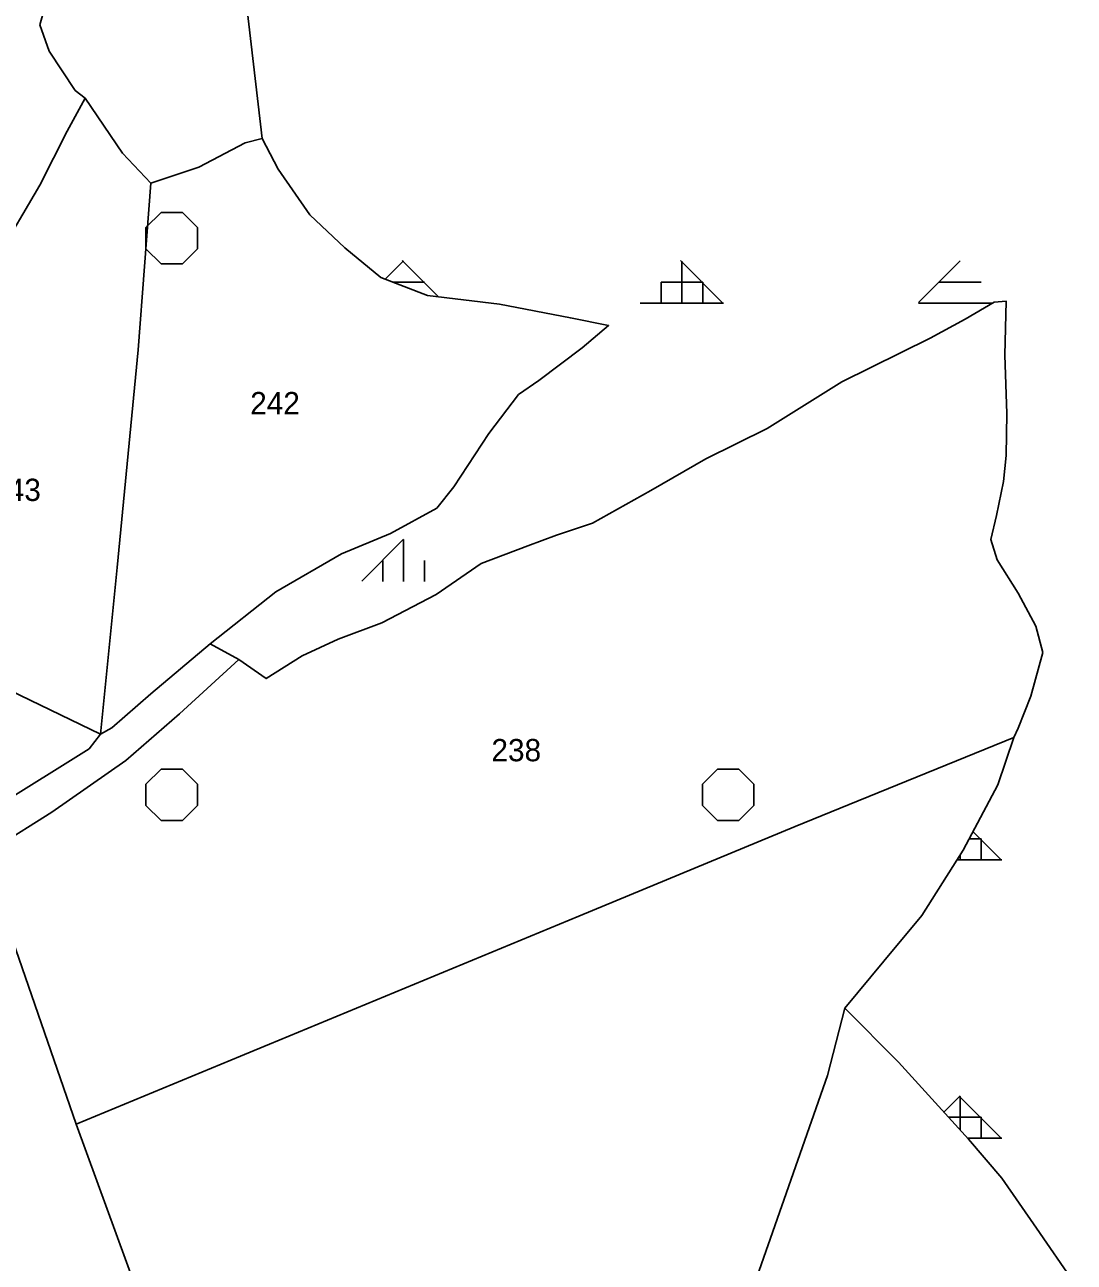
# Model space of a CAD drawing. Extents: x 410727 to 412947, y 4463506 to 4466382.
# Drawn here: x 412194.6 to 412383.2, y 4465413.6 to 4465635.8 of the extents above; entities that cross this region are included whole.
import ezdxf

# ---------------------------------------------------------------- set-up
doc = ezdxf.new("R2010")
doc.units = 0
for name, color, linetype in [('ADAKENARI', 7, 'Continuous'), ('KDS_PARSEL_NO', 7, 'Continuous'), ('KDS_PL', 7, 'Continuous'), ('PL_AYA_ORMAN', 7, 'Continuous'), ('PL_KA_TARIM_DIGER', 7, 'Continuous'), ('TR_ORMAN', 7, 'Continuous'), ('TR_TARIMALANI', 7, 'Continuous')]:
    doc.layers.add(name, color=color, linetype=linetype)

msp = doc.modelspace()

# ---------------------------------------------------------------- linework, layer by layer
at = {"layer": 'ADAKENARI'}
for p, q in [((412237.26, 4465615.42), (412234.44, 4465639.54)), ((412240.11, 4465609.88), (412237.26, 4465615.42)), ((412245.82, 4465601.68), (412240.11, 4465609.88)), ((412252.1, 4465595.77), (412245.82, 4465601.68)), ((412258.58, 4465590.43), (412252.1, 4465595.77)), ((412266.95, 4465587.19), (412258.58, 4465590.43)), ((412279.89, 4465585.66), (412266.95, 4465587.19)), ((412292.65, 4465583.18), (412279.89, 4465585.66)), ((412368.8, 4465586.04), (412363.6, 4465582.99)), ((412370.95, 4465586.17), (412368.8, 4465586.04)), ((412370.7, 4465576.52), (412370.95, 4465586.17)), ((412299.5, 4465581.85), (412292.65, 4465583.18)), ((412363.6, 4465582.99), (412357.27, 4465579.57)), ((412294.74, 4465577.84), (412299.5, 4465581.85)), ((412286.94, 4465571.93), (412294.74, 4465577.84)), ((412357.27, 4465579.57), (412341.44, 4465571.7)), ((412371.08, 4465565.99), (412370.7, 4465576.52)), ((412283.32, 4465569.45), (412286.94, 4465571.93)), ((412341.44, 4465571.7), (412328.02, 4465563.33)), ((412277.99, 4465562.4), (412283.32, 4465569.45)), ((412370.95, 4465558.5), (412371.08, 4465565.99)), ((412271.71, 4465552.86), (412277.99, 4465562.4)), ((412328.02, 4465563.33), (412317, 4465557.87)), ((412317, 4465557.87), (412307.12, 4465552.16)), ((412370.45, 4465553.81), (412370.95, 4465558.5)), ((412369.18, 4465547.72), (412370.45, 4465553.81)), ((412268.66, 4465549.04), (412271.71, 4465552.86)), ((412307.12, 4465552.16), (412296.61, 4465546.32)), ((412260.29, 4465544.47), (412268.66, 4465549.04)), ((412368.17, 4465543.4), (412369.18, 4465547.72)), ((412251.53, 4465540.84), (412260.29, 4465544.47)), ((412296.61, 4465546.32), (412290.15, 4465544.16)), ((412284.96, 4465542.26), (412276.6, 4465539.09)), ((412290.15, 4465544.16), (412284.96, 4465542.26)), ((412290.15, 4465544.16), (412284.96, 4465542.26)), ((412369.3, 4465539.72), (412368.17, 4465543.4)), ((412239.73, 4465533.98), (412251.53, 4465540.84)), ((412276.6, 4465539.09), (412268.5, 4465533.51)), ((412373.1, 4465533.76), (412369.3, 4465539.72)), ((412227.93, 4465524.63), (412239.73, 4465533.98)), ((412268.5, 4465533.51), (412258.74, 4465528.43)), ((412376.27, 4465527.79), (412373.1, 4465533.76)), ((412258.74, 4465528.43), (412250.89, 4465525.51)), ((412377.54, 4465523.1), (412376.27, 4465527.79)), ((412233.04, 4465521.83), (412227.93, 4465524.63)), ((412250.89, 4465525.51), (412244.43, 4465522.47)), ((412244.43, 4465522.47), (412237.98, 4465518.41)), ((412375.38, 4465515.23), (412377.54, 4465523.1)), ((412237.98, 4465518.41), (412233.04, 4465521.83)), ((412373.1, 4465509.52), (412375.38, 4465515.23)), ((412372.33, 4465507.8), (412373.1, 4465509.52)), ((412372.33, 4465507.8), (412373.1, 4465509.52)), ((412369.44, 4465499.29), (412372.33, 4465507.8)), ((412363.22, 4465487.58), (412369.44, 4465499.29)), ((412355.78, 4465475.87), (412363.22, 4465487.58)), ((412348.96, 4465467.64), (412355.78, 4465475.87)), ((412341.94, 4465459.2), (412348.96, 4465467.64)), ((412351.61, 4465449.5), (412341.94, 4465459.2)), ((412364.2, 4465435.68), (412351.61, 4465449.5)), ((412370.19, 4465428.68), (412364.2, 4465435.68)), ((412376.38, 4465419.67), (412370.19, 4465428.68)), ((412383.18, 4465409.86), (412376.38, 4465419.67))]:
    msp.add_line(p, q, dxfattribs=at)
at = {"layer": 'KDS_PL'}
for p, q in [((412198.76, 4465640.96), (412197.27, 4465635.83)), ((412197.27, 4465635.83), (412198.98, 4465631.12)), ((412198.98, 4465631.12), (412203.67, 4465624.06)), ((412202.23, 4465616.75), (412205.47, 4465622.66)), ((412203.67, 4465624.06), (412205.47, 4465622.66)), ((412205.47, 4465622.66), (412212.13, 4465612.75)), ((412197.29, 4465607.03), (412202.23, 4465616.75)), ((412234.21, 4465614.65), (412237.26, 4465615.42)), ((412237.26, 4465615.42), (412240.11, 4465609.88)), ((412225.84, 4465610.27), (412234.21, 4465614.65)), ((412212.13, 4465612.75), (412217.27, 4465607.41)), ((412217.27, 4465607.41), (412225.84, 4465610.27)), ((412240.11, 4465609.88), (412245.82, 4465601.68)), ((412182.06, 4465581.09), (412197.29, 4465607.03)), ((412217.27, 4465607.41), (412214.99, 4465577.46)), ((412245.82, 4465601.68), (412252.1, 4465595.77)), ((412252.1, 4465595.77), (412258.58, 4465590.43)), ((412258.58, 4465590.43), (412266.95, 4465587.19)), ((412266.95, 4465587.19), (412279.89, 4465585.66)), ((412279.89, 4465585.66), (412292.65, 4465583.18)), ((412363.6, 4465582.99), (412368.8, 4465586.04)), ((412368.8, 4465586.04), (412370.95, 4465586.17)), ((412370.95, 4465586.17), (412370.7, 4465576.52)), ((412292.65, 4465583.18), (412299.5, 4465581.85)), ((412357.27, 4465579.57), (412363.6, 4465582.99)), ((412299.5, 4465581.85), (412294.74, 4465577.84)), ((412294.74, 4465577.84), (412286.94, 4465571.93)), ((412341.44, 4465571.7), (412357.27, 4465579.57)), ((412214.99, 4465577.46), (412211.18, 4465538.37)), ((412370.7, 4465576.52), (412371.08, 4465565.99)), ((412286.94, 4465571.93), (412283.32, 4465569.45)), ((412328.02, 4465563.33), (412341.44, 4465571.7)), ((412283.32, 4465569.45), (412277.99, 4465562.4)), ((412371.08, 4465565.99), (412370.95, 4465558.5)), ((412277.99, 4465562.4), (412271.71, 4465552.86)), ((412317, 4465557.87), (412328.02, 4465563.33)), ((412307.12, 4465552.16), (412317, 4465557.87)), ((412370.95, 4465558.5), (412370.45, 4465553.81)), ((412370.45, 4465553.81), (412369.18, 4465547.72)), ((412271.71, 4465552.86), (412268.66, 4465549.04)), ((412296.61, 4465546.32), (412307.12, 4465552.16)), ((412268.66, 4465549.04), (412260.29, 4465544.47)), ((412369.18, 4465547.72), (412368.17, 4465543.4)), ((412260.29, 4465544.47), (412251.53, 4465540.84)), ((412290.15, 4465544.16), (412296.61, 4465546.32)), ((412276.6, 4465539.09), (412284.96, 4465542.26)), ((412284.96, 4465542.26), (412290.15, 4465544.16)), ((412368.17, 4465543.4), (412369.3, 4465539.72)), ((412251.53, 4465540.84), (412239.73, 4465533.98)), ((412211.18, 4465538.37), (412208.18, 4465508.42)), ((412268.5, 4465533.51), (412276.6, 4465539.09)), ((412369.3, 4465539.72), (412373.1, 4465533.76)), ((412239.73, 4465533.98), (412227.93, 4465524.63)), ((412258.74, 4465528.43), (412268.5, 4465533.51)), ((412373.1, 4465533.76), (412376.27, 4465527.79)), ((412250.89, 4465525.51), (412258.74, 4465528.43)), ((412376.27, 4465527.79), (412377.54, 4465523.1)), ((412227.93, 4465524.63), (412217.27, 4465515.67)), ((412227.93, 4465524.63), (412233.04, 4465521.83)), ((412244.43, 4465522.47), (412250.89, 4465525.51)), ((412237.98, 4465518.41), (412244.43, 4465522.47)), ((412377.54, 4465523.1), (412375.38, 4465515.23)), ((412222.4, 4465512.06), (412233.04, 4465521.83)), ((412233.04, 4465521.83), (412237.98, 4465518.41)), ((412208.18, 4465508.42), (412191.95, 4465516.24)), ((412217.27, 4465515.67), (412210.23, 4465509.57)), ((412375.38, 4465515.23), (412373.1, 4465509.52)), ((412212.77, 4465503.68), (412222.4, 4465512.06)), ((412210.23, 4465509.57), (412208.18, 4465508.42)), ((412373.1, 4465509.52), (412372.33, 4465507.8)), ((412206.17, 4465505.77), (412208.18, 4465508.42)), ((412372.33, 4465507.8), (412342.73, 4465495.79)), ((412369.44, 4465499.29), (412372.33, 4465507.8)), ((412173.15, 4465485.18), (412206.17, 4465505.77)), ((412199.48, 4465494.42), (412212.77, 4465503.68)), ((412363.22, 4465487.58), (412369.44, 4465499.29)), ((412342.73, 4465495.79), (412333.02, 4465491.83)), ((412186.94, 4465486.55), (412199.48, 4465494.42)), ((412333.02, 4465491.83), (412294.16, 4465475.71)), ((412355.78, 4465475.87), (412363.22, 4465487.58)), ((412203.85, 4465438.37), (412187.36, 4465485.9)), ((412294.16, 4465475.71), (412203.85, 4465438.37)), ((412348.96, 4465467.64), (412355.78, 4465475.87)), ((412341.94, 4465459.2), (412348.96, 4465467.64)), ((412338.85, 4465447.1), (412341.94, 4465459.2)), ((412341.94, 4465459.2), (412351.61, 4465449.5)), ((412351.61, 4465449.5), (412364.2, 4465435.68)), ((412324.53, 4465406.29), (412338.85, 4465447.1)), ((412203.85, 4465438.37), (412217.2, 4465401.77)), ((412364.2, 4465435.68), (412370.19, 4465428.68)), ((412370.19, 4465428.68), (412376.38, 4465419.67)), ((412376.38, 4465419.67), (412383.18, 4465409.86))]:
    msp.add_line(p, q, dxfattribs=at)
at = {"layer": 'PL_AYA_ORMAN'}
msp.add_lwpolyline([(412234.44, 4465639.54), (412237.26, 4465615.42), (412240.11, 4465609.88), (412245.82, 4465601.68), (412252.1, 4465595.77), (412258.58, 4465590.43), (412266.95, 4465587.19), (412279.89, 4465585.66), (412292.65, 4465583.18), (412299.5, 4465581.85), (412294.74, 4465577.84), (412286.94, 4465571.93), (412283.32, 4465569.45), (412277.99, 4465562.4), (412271.71, 4465552.86), (412268.66, 4465549.04), (412260.29, 4465544.47), (412251.53, 4465540.84), (412239.73, 4465533.98), (412227.93, 4465524.63), (412233.04, 4465521.83), (412237.98, 4465518.41), (412244.43, 4465522.47), (412250.89, 4465525.51), (412258.74, 4465528.43), (412268.5, 4465533.51), (412276.6, 4465539.09), (412284.96, 4465542.26), (412290.15, 4465544.16), (412296.61, 4465546.32), (412307.12, 4465552.16), (412317, 4465557.87), (412328.02, 4465563.33), (412341.44, 4465571.7), (412357.27, 4465579.57), (412363.6, 4465582.99), (412368.8, 4465586.04), (412370.95, 4465586.17), (412370.7, 4465576.52), (412371.08, 4465565.99), (412370.95, 4465558.5), (412370.45, 4465553.81), (412369.18, 4465547.72), (412368.17, 4465543.4), (412369.3, 4465539.72), (412373.1, 4465533.76), (412376.27, 4465527.79), (412377.54, 4465523.1), (412375.38, 4465515.23), (412373.1, 4465509.52), (412372.33, 4465507.8), (412369.44, 4465499.29), (412363.22, 4465487.58), (412355.78, 4465475.87), (412348.96, 4465467.64), (412341.94, 4465459.2), (412351.61, 4465449.5), (412364.2, 4465435.68), (412370.19, 4465428.68), (412376.38, 4465419.67), (412383.18, 4465409.86)], dxfattribs=at)
at = {"layer": 'PL_KA_TARIM_DIGER'}
msp.add_lwpolyline([(412234.44, 4465639.54), (412237.26, 4465615.42), (412240.11, 4465609.88), (412245.82, 4465601.68), (412252.1, 4465595.77), (412258.58, 4465590.43), (412266.95, 4465587.19), (412279.89, 4465585.66), (412292.65, 4465583.18), (412299.5, 4465581.85), (412294.74, 4465577.84), (412286.94, 4465571.93), (412283.32, 4465569.45), (412277.99, 4465562.4), (412271.71, 4465552.86), (412268.66, 4465549.04), (412260.29, 4465544.47), (412251.53, 4465540.84), (412239.73, 4465533.98), (412227.93, 4465524.63), (412233.04, 4465521.83), (412237.98, 4465518.41), (412244.43, 4465522.47), (412250.89, 4465525.51), (412258.74, 4465528.43), (412268.5, 4465533.51), (412276.6, 4465539.09), (412284.96, 4465542.26), (412290.15, 4465544.16), (412296.61, 4465546.32), (412307.12, 4465552.16), (412317, 4465557.87), (412328.02, 4465563.33), (412341.44, 4465571.7), (412357.27, 4465579.57), (412363.6, 4465582.99), (412368.8, 4465586.04), (412370.95, 4465586.17), (412370.7, 4465576.52), (412371.08, 4465565.99), (412370.95, 4465558.5), (412370.45, 4465553.81), (412369.18, 4465547.72), (412368.17, 4465543.4), (412369.3, 4465539.72), (412373.1, 4465533.76), (412376.27, 4465527.79), (412377.54, 4465523.1), (412375.38, 4465515.23), (412373.1, 4465509.52), (412372.33, 4465507.8), (412369.44, 4465499.29), (412363.22, 4465487.58), (412355.78, 4465475.87), (412348.96, 4465467.64), (412341.94, 4465459.2), (412351.61, 4465449.5), (412364.2, 4465435.68), (412370.19, 4465428.68), (412376.38, 4465419.67), (412383.18, 4465409.86)], dxfattribs=at)
at = {"layer": 'TR_ORMAN'}
for p, q in [((412259.37, 4465590.12), (412262.66, 4465593.41)), ((412259.37, 4465590.12), (412262.66, 4465593.41)), ((412268.94, 4465586.96), (412262.41, 4465593.48)), ((412268.94, 4465586.96), (412262.41, 4465593.48)), ((412319.9, 4465585.98), (412312.4, 4465593.48)), ((412319.9, 4465585.98), (412312.4, 4465593.48)), ((412312.67, 4465585.86), (412312.67, 4465593.36)), ((412312.67, 4465585.86), (412312.67, 4465593.36)), ((412355.16, 4465585.93), (412362.66, 4465593.43)), ((412260.7, 4465589.61), (412266.42, 4465589.61)), ((412260.7, 4465589.61), (412266.42, 4465589.61)), ((412308.92, 4465585.86), (412308.92, 4465589.61)), ((412308.92, 4465589.61), (412316.42, 4465589.61)), ((412308.92, 4465585.86), (412308.92, 4465589.61)), ((412308.92, 4465589.61), (412316.42, 4465589.61)), ((412316.42, 4465585.86), (412316.42, 4465589.61)), ((412316.42, 4465585.86), (412316.42, 4465589.61)), ((412358.92, 4465589.61), (412366.42, 4465589.61)), ((412305.17, 4465585.86), (412320.17, 4465585.86)), ((412305.17, 4465585.86), (412320.17, 4465585.86)), ((412355.17, 4465585.86), (412368.49, 4465585.86)), ((412255.16, 4465535.92), (412262.66, 4465543.42)), ((412255.16, 4465535.92), (412262.66, 4465543.42)), ((412262.67, 4465535.86), (412262.67, 4465543.36)), ((412262.67, 4465535.86), (412262.67, 4465543.36)), ((412258.92, 4465535.86), (412258.92, 4465539.61)), ((412258.92, 4465535.86), (412258.92, 4465539.61)), ((412266.42, 4465535.86), (412266.42, 4465539.61)), ((412266.42, 4465535.86), (412266.42, 4465539.61)), ((412364.3, 4465489.61), (412366.42, 4465489.61)), ((412364.3, 4465489.61), (412366.42, 4465489.61)), ((412369.96, 4465485.93), (412364.99, 4465490.9)), ((412369.96, 4465485.93), (412364.99, 4465490.9)), ((412366.42, 4465485.86), (412366.42, 4465489.61)), ((412366.42, 4465485.86), (412366.42, 4465489.61)), ((412362.67, 4465485.86), (412362.67, 4465486.71)), ((412362.67, 4465485.86), (412362.67, 4465486.71)), ((412362.13, 4465485.86), (412370.17, 4465485.86)), ((412362.13, 4465485.86), (412370.17, 4465485.86)), ((412359.76, 4465440.55), (412362.66, 4465443.45)), ((412359.76, 4465440.55), (412362.66, 4465443.45)), ((412369.99, 4465435.91), (412362.49, 4465443.41)), ((412369.99, 4465435.91), (412362.49, 4465443.41)), ((412362.67, 4465437.36), (412362.67, 4465443.36)), ((412362.67, 4465437.36), (412362.67, 4465443.36)), ((412360.62, 4465439.61), (412366.42, 4465439.61)), ((412360.62, 4465439.61), (412366.42, 4465439.61)), ((412366.42, 4465435.86), (412366.42, 4465439.61)), ((412366.42, 4465435.86), (412366.42, 4465439.61)), ((412364.03, 4465435.86), (412370.17, 4465435.86)), ((412364.03, 4465435.86), (412370.17, 4465435.86))]:
    msp.add_line(p, q, dxfattribs=at)
at = {"layer": 'TR_TARIMALANI'}
for p, q in [((412216.37, 4465599.43), (412219.08, 4465602.14)), ((412216.37, 4465599.43), (412219.08, 4465602.14)), ((412219.08, 4465602.14), (412222.91, 4465602.14)), ((412219.08, 4465602.14), (412222.91, 4465602.14)), ((412225.62, 4465599.43), (412222.91, 4465602.14)), ((412225.62, 4465599.43), (412222.91, 4465602.14)), ((412216.37, 4465595.6), (412216.37, 4465599.43)), ((412216.37, 4465595.6), (412216.37, 4465599.43)), ((412225.62, 4465595.6), (412225.62, 4465599.43)), ((412225.62, 4465595.6), (412225.62, 4465599.43)), ((412219.08, 4465592.89), (412216.37, 4465595.6)), ((412219.08, 4465592.89), (412216.37, 4465595.6)), ((412222.91, 4465592.89), (412225.62, 4465595.6)), ((412222.91, 4465592.89), (412225.62, 4465595.6)), ((412219.08, 4465592.89), (412222.91, 4465592.89)), ((412219.08, 4465592.89), (412222.91, 4465592.89)), ((412216.37, 4465499.43), (412219.08, 4465502.14)), ((412216.37, 4465499.43), (412219.08, 4465502.14)), ((412219.08, 4465502.14), (412222.91, 4465502.14)), ((412219.08, 4465502.14), (412222.91, 4465502.14)), ((412225.62, 4465499.43), (412222.91, 4465502.14)), ((412225.62, 4465499.43), (412222.91, 4465502.14)), ((412316.37, 4465499.43), (412319.08, 4465502.14)), ((412316.37, 4465499.43), (412319.08, 4465502.14)), ((412319.08, 4465502.14), (412322.91, 4465502.14)), ((412319.08, 4465502.14), (412322.91, 4465502.14)), ((412325.62, 4465499.43), (412322.91, 4465502.14)), ((412325.62, 4465499.43), (412322.91, 4465502.14)), ((412216.37, 4465495.6), (412216.37, 4465499.43)), ((412216.37, 4465495.6), (412216.37, 4465499.43)), ((412225.62, 4465495.6), (412225.62, 4465499.43)), ((412225.62, 4465495.6), (412225.62, 4465499.43)), ((412316.37, 4465495.6), (412316.37, 4465499.43)), ((412316.37, 4465495.6), (412316.37, 4465499.43)), ((412325.62, 4465495.6), (412325.62, 4465499.43)), ((412325.62, 4465495.6), (412325.62, 4465499.43)), ((412219.08, 4465492.89), (412216.37, 4465495.6)), ((412219.08, 4465492.89), (412216.37, 4465495.6)), ((412222.91, 4465492.89), (412225.62, 4465495.6)), ((412222.91, 4465492.89), (412225.62, 4465495.6)), ((412319.08, 4465492.89), (412316.37, 4465495.6)), ((412319.08, 4465492.89), (412316.37, 4465495.6)), ((412322.91, 4465492.89), (412325.62, 4465495.6)), ((412322.91, 4465492.89), (412325.62, 4465495.6)), ((412219.08, 4465492.89), (412222.91, 4465492.89)), ((412219.08, 4465492.89), (412222.91, 4465492.89)), ((412319.08, 4465492.89), (412322.91, 4465492.89)), ((412319.08, 4465492.89), (412322.91, 4465492.89))]:
    msp.add_line(p, q, dxfattribs=at)

# ---------------------------------------------------------------- texts
at = {"layer": 'KDS_PARSEL_NO'}
for s, p in [('242', (412235.1, 4465565.88)), ('243', (412188.56, 4465550.3)), ('238', (412278.45, 4465503.55))]:
    msp.add_text(s, height=4, dxfattribs=at).set_placement(p)

doc.saveas('drawing.dxf')
